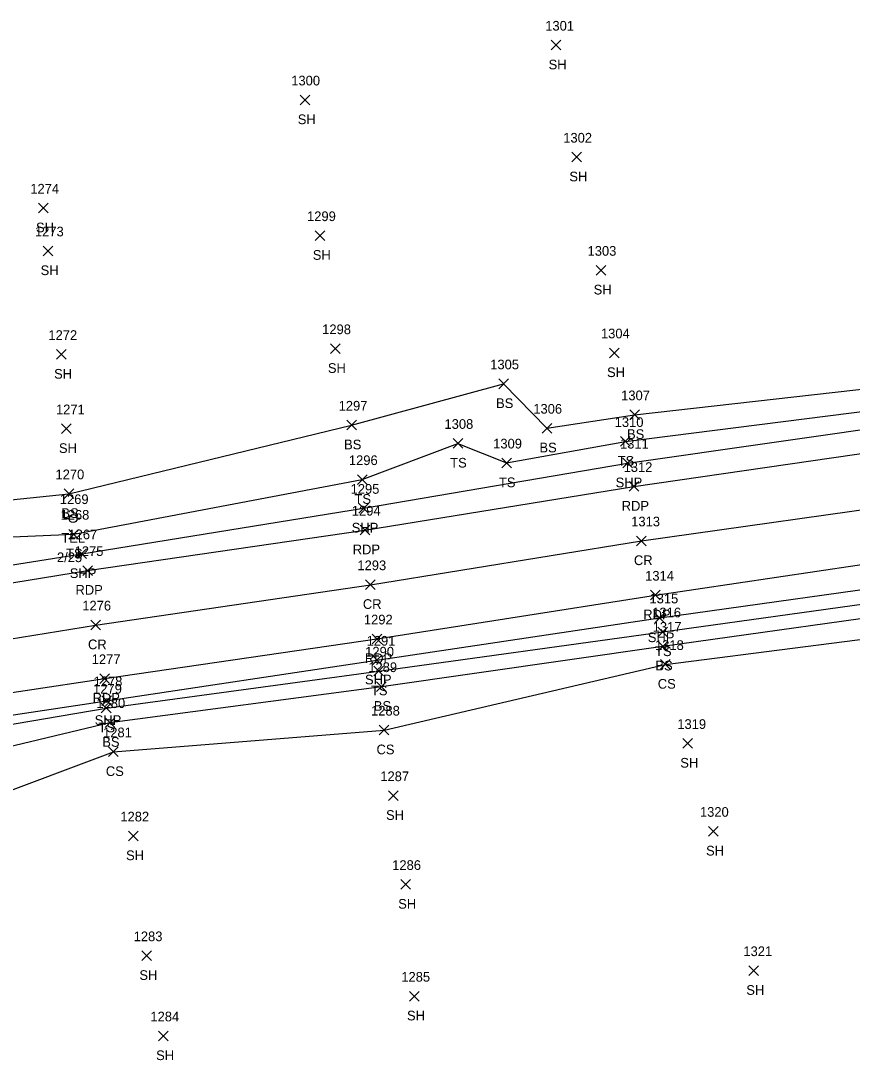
# Model space of a CAD drawing. Extents: x 1497084 to 1499861, y 734741 to 735567.
# Drawn here: x 1498487 to 1498658.8, y 735242.1 to 735456.8 of the extents above; entities that cross this region are included whole.
import ezdxf

# ---------------------------------------------------------------- set-up
doc = ezdxf.new("R2010")
doc.units = 0
for name, color, linetype in [('L_A', 7, 'Continuous'), ('L_I', 7, 'Continuous'), ('L_TIC', 7, 'Continuous'), ('LELB', 7, 'Continuous'), ('P_A', 7, 'Continuous'), ('P_I', 7, 'Continuous'), ('P_TIC', 7, 'Continuous'), ('PET', 7, 'Continuous'), ('PRC', 7, 'Continuous'), ('PSP', 7, 'Continuous'), ('U_A', 7, 'Continuous'), ('U_C', 7, 'Continuous'), ('U_I', 7, 'Continuous'), ('UP', 7, 'Continuous')]:
    doc.layers.add(name, color=color, linetype=linetype)

msp = doc.modelspace()

# ---------------------------------------------------------------- linework, layer by layer
at = {"layer": 'L_TIC'}
for points in [[(1498596.59, 735450.76), (1498598.59, 735452.76)], [(1498598.59, 735450.76), (1498596.59, 735452.76)], [(1498544.77, 735439.44), (1498546.77, 735441.44)], [(1498546.77, 735439.44), (1498544.77, 735441.44)], [(1498600.88, 735427.63), (1498602.88, 735429.63)], [(1498602.88, 735427.63), (1498600.88, 735429.63)], [(1498490.69, 735417.1), (1498492.69, 735419.1)], [(1498492.69, 735417.1), (1498490.69, 735419.1)], [(1498547.88, 735411.42), (1498549.88, 735413.42)], [(1498549.88, 735411.42), (1498547.88, 735413.42)], [(1498491.64, 735408.26), (1498493.64, 735410.26)], [(1498493.64, 735408.26), (1498491.64, 735410.26)], [(1498605.9, 735404.26), (1498607.9, 735406.26)], [(1498607.9, 735404.26), (1498605.9, 735406.26)], [(1498550.99, 735388.06), (1498552.99, 735390.06)], [(1498552.99, 735388.06), (1498550.99, 735390.06)], [(1498494.42, 735386.87), (1498496.42, 735388.87)], [(1498496.42, 735386.87), (1498494.42, 735388.87)], [(1498608.67, 735387.2), (1498610.67, 735389.2)], [(1498610.67, 735387.2), (1498608.67, 735389.2)], [(1498585.79, 735380.8), (1498587.79, 735382.8)], [(1498587.79, 735380.8), (1498585.79, 735382.8)], [(1498612.85, 735374.41), (1498614.85, 735376.41)], [(1498614.85, 735374.41), (1498612.85, 735376.41)], [(1498495.42, 735371.52), (1498497.42, 735373.52)], [(1498497.42, 735371.52), (1498495.42, 735373.52)], [(1498554.39, 735372.27), (1498556.39, 735374.27)], [(1498556.39, 735372.27), (1498554.39, 735374.27)], [(1498594.75, 735371.64), (1498596.75, 735373.64)], [(1498596.75, 735371.64), (1498594.75, 735373.64)], [(1498610.95, 735368.89), (1498612.95, 735370.89)], [(1498612.95, 735368.89), (1498610.95, 735370.89)], [(1498576.34, 735368.5), (1498578.34, 735370.5)], [(1498578.34, 735368.5), (1498576.34, 735370.5)], [(1498586.41, 735364.45), (1498588.41, 735366.45)], [(1498588.41, 735364.45), (1498586.41, 735366.45)], [(1498556.57, 735361.02), (1498558.57, 735363.02)], [(1498558.57, 735361.02), (1498556.57, 735363.02)], [(1498495.97, 735358.09), (1498497.97, 735360.09)], [(1498497.97, 735358.09), (1498495.97, 735360.09)], [(1498496.98, 735349.74), (1498498.98, 735351.74)], [(1498498.98, 735349.74), (1498496.98, 735351.74)], [(1498618.67, 735329.56), (1498620.67, 735331.56)], [(1498620.67, 735329.56), (1498618.67, 735331.56)], [(1498618.71, 735326.6), (1498620.71, 735328.6)], [(1498620.71, 735326.6), (1498618.71, 735328.6)], [(1498559.97, 735321.47), (1498561.97, 735323.47)], [(1498561.97, 735321.47), (1498559.97, 735323.47)], [(1498619.2, 735322.83), (1498621.2, 735324.83)], [(1498621.2, 735322.83), (1498619.2, 735324.83)], [(1498560.53, 735318.26), (1498562.53, 735320.26)], [(1498562.53, 735318.26), (1498560.53, 735320.26)], [(1498503.67, 735313.81), (1498505.67, 735315.81)], [(1498505.67, 735313.81), (1498503.67, 735315.81)], [(1498504.43, 735310.83), (1498506.43, 735312.83)], [(1498506.43, 735310.83), (1498504.43, 735312.83)], [(1498561.09, 735309.28), (1498563.09, 735311.28)], [(1498563.09, 735309.28), (1498561.09, 735311.28)], [(1498623.8, 735306.52), (1498625.8, 735308.52)], [(1498625.8, 735306.52), (1498623.8, 735308.52)], [(1498505.16, 735304.79), (1498507.16, 735306.79)], [(1498507.16, 735304.79), (1498505.16, 735306.79)], [(1498563.01, 735295.73), (1498565.01, 735297.73)], [(1498565.01, 735295.73), (1498563.01, 735297.73)], [(1498509.29, 735287.41), (1498511.29, 735289.41)], [(1498511.29, 735287.41), (1498509.29, 735289.41)], [(1498629.13, 735288.37), (1498631.13, 735290.37)], [(1498631.13, 735288.37), (1498629.13, 735290.37)], [(1498565.52, 735277.39), (1498567.52, 735279.39)], [(1498567.52, 735277.39), (1498565.52, 735279.39)], [(1498512.05, 735262.67), (1498514.05, 735264.67)], [(1498514.05, 735262.67), (1498512.05, 735264.67)], [(1498637.44, 735259.59), (1498639.44, 735261.59)], [(1498639.44, 735259.59), (1498637.44, 735261.59)], [(1498567.34, 735254.31), (1498569.34, 735256.31)], [(1498569.34, 735254.31), (1498567.34, 735256.31)], [(1498515.5, 735246.11), (1498517.5, 735248.11)], [(1498517.5, 735246.11), (1498515.5, 735248.11)]]:
    msp.add_lwpolyline(points, dxfattribs=at)
at = {"layer": 'LELB'}
for points in [[(1498337.56, 735327.03), (1498345.07, 735328.8), (1498360.02, 735336.05), (1498371.93, 735339.18), (1498383.26, 735341.12), (1498406.51, 735345.51), (1498447.67, 735353.97), (1498496.97, 735359.09), (1498555.39, 735373.27), (1498586.79, 735381.8), (1498595.75, 735372.64), (1498613.85, 735375.41), (1498671.76, 735381.92), (1498728.97, 735390.65), (1498788.67, 735399.74), (1498809.3, 735404.43), (1498807.97, 735434.2)], [(1498337.34, 735322.86), (1498344.97, 735324.75), (1498384.58, 735334.28), (1498409.2, 735337.4), (1498355.01, 735326.99), (1498382.45, 735331.79), (1498397.41, 735335.39), (1498428.62, 735342.29), (1498447.37, 735348.53), (1498497.98, 735350.74), (1498557.57, 735362.02), (1498577.34, 735369.5), (1498587.41, 735365.45), (1498611.95, 735369.89), (1498672.2, 735377.52), (1498729.57, 735386.75), (1498788.99, 735396.46), (1498814.15, 735401.69), (1498836.02, 735409.82), (1498851.62, 735410.69)], [(1498435.91, 735287.74), (1498479.86, 735295.91), (1498506.16, 735305.79), (1498562.09, 735310.28), (1498620.2, 735323.83), (1498678.14, 735331.24), (1498740.72, 735343.34), (1498795.48, 735350.02), (1498845.2, 735354.12), (1498873.2, 735358.8), (1498904.58, 735361.51), (1498941.92, 735355.1), (1499002.35, 735368.44), (1499018.4, 735380.28), (1499017.69, 735389.23)], [(1498348.47, 735290.66), (1498349.3, 735292.12), (1498356.63, 735290), (1498367.4, 735288.15), (1498383.02, 735293.44), (1498402.41, 735293.85), (1498412.25, 735297.62), (1498434.81, 735303.59), (1498479.54, 735310.53), (1498504.67, 735314.81), (1498560.97, 735322.47), (1498619.67, 735330.56), (1498677.12, 735338.58), (1498739.34, 735349.1), (1498794.83, 735357.09), (1498843.56, 735364.4), (1498863.08, 735369.39)], [(1498347.81, 735289.73), (1498349.19, 735291.09), (1498355.19, 735287.19), (1498360.89, 735284.04), (1498368.96, 735282.7), (1498386.86, 735285.14), (1498402.12, 735288.93), (1498434.54, 735297.05), (1498479.17, 735305.56), (1498505.43, 735311.83), (1498561.53, 735319.26), (1498619.71, 735327.6), (1498677.77, 735335.72), (1498739.77, 735346.92), (1498794.9, 735353.46), (1498843.96, 735361.06), (1498867.57, 735365.18)]]:
    msp.add_lwpolyline(points, dxfattribs=at)
at = {"layer": 'P_TIC'}
for points in [[(1498611.39, 735364.43), (1498613.39, 735366.43)], [(1498613.39, 735364.43), (1498611.39, 735366.43)], [(1498612.71, 735359.6), (1498614.71, 735361.6)], [(1498614.71, 735359.6), (1498612.71, 735361.6)], [(1498556.87, 735355.09), (1498558.87, 735357.09)], [(1498558.87, 735355.09), (1498556.87, 735357.09)], [(1498557.12, 735350.59), (1498559.12, 735352.59)], [(1498559.12, 735350.59), (1498557.12, 735352.59)], [(1498614.27, 735348.36), (1498616.27, 735350.36)], [(1498616.27, 735348.36), (1498614.27, 735350.36)], [(1498498.61, 735345.69), (1498500.61, 735347.69)], [(1498500.61, 735345.69), (1498498.61, 735347.69)], [(1498499.84, 735342.24), (1498501.84, 735344.24)], [(1498501.84, 735342.24), (1498499.84, 735344.24)], [(1498558.28, 735339.31), (1498560.28, 735341.31)], [(1498560.28, 735339.31), (1498558.28, 735341.31)], [(1498617.15, 735337.15), (1498619.15, 735339.15)], [(1498619.15, 735337.15), (1498617.15, 735339.15)], [(1498618.04, 735332.45), (1498620.04, 735334.45)], [(1498620.04, 735332.45), (1498618.04, 735334.45)], [(1498501.48, 735330.98), (1498503.48, 735332.98)], [(1498503.48, 735330.98), (1498501.48, 735332.98)], [(1498559.62, 735328.11), (1498561.62, 735330.11)], [(1498561.62, 735328.11), (1498559.62, 735330.11)], [(1498559.61, 735323.72), (1498561.61, 735325.72)], [(1498561.61, 735323.72), (1498559.61, 735325.72)], [(1498503.37, 735319.92), (1498505.37, 735321.92)], [(1498505.37, 735319.92), (1498503.37, 735321.92)], [(1498503.77, 735315.34), (1498505.77, 735317.34)], [(1498505.77, 735315.34), (1498503.77, 735317.34)]]:
    msp.add_lwpolyline(points, dxfattribs=at)
at = {"layer": 'PET'}
for points in [[(1498338.16, 735318.88), (1498357.92, 735321.69), (1498398.8, 735327.5), (1498451.3, 735335.22), (1498500.84, 735343.24), (1498558.12, 735351.59), (1498613.71, 735360.6), (1498673.07, 735369.22), (1498732.2, 735378.98), (1498789.96, 735387.82), (1498838.32, 735395.91), (1498888.99, 735404.3)], [(1498338.16, 735318.88), (1498339.87, 735308.1), (1498341.54, 735297.2), (1498360.21, 735300.18), (1498403.13, 735306.7), (1498454.97, 735313.53), (1498504.37, 735320.92), (1498560.62, 735329.11), (1498618.15, 735338.15), (1498676.47, 735346.79), (1498736.79, 735356.32), (1498793.85, 735365.14), (1498842.44, 735373.21), (1498892.67, 735381.87)]]:
    msp.add_lwpolyline(points, dxfattribs=at)
at = {"layer": 'PRC'}
msp.add_lwpolyline([(1498339.87, 735308.1), (1498359.7, 735310.92), (1498400.74, 735317.79), (1498454.01, 735324.13), (1498502.48, 735331.98), (1498559.28, 735340.31), (1498615.27, 735349.36), (1498674.88, 735357.8), (1498734.12, 735367.05), (1498791.71, 735376.05), (1498839.89, 735384.37), (1498890.74, 735392.79)], dxfattribs=at)
at = {"layer": 'PSP'}
for points in [[(1498357.92, 735321.69), (1498398.08, 735329.19), (1498452.34, 735339.17), (1498499.61, 735346.69), (1498557.87, 735356.09), (1498612.39, 735365.43), (1498672.54, 735374.02), (1498730.82, 735383.15), (1498789.68, 735392.14), (1498809.84, 735395.77), (1498833.8, 735399.85), (1498855.6, 735403.69)], [(1498360.21, 735300.18), (1498403.51, 735303.5), (1498455.72, 735308.98), (1498504.77, 735316.34), (1498560.61, 735324.72), (1498619.04, 735333.45), (1498677.11, 735341.57), (1498738.32, 735351.55), (1498794.38, 735360.63), (1498843.61, 735368.57), (1498860.46, 735371.23)]]:
    msp.add_lwpolyline(points, dxfattribs=at)
at = {"layer": 'UP'}
for p, q in [((1498496.18, 735353.96), (1498497.01, 735353.96)), ((1498497.84, 735353.97), (1498497.84, 735353.97)), ((1498499.51, 735353.97), (1498498.67, 735353.97)), ((1498498.67, 735353.97), (1498498.67, 735353.97)), ((1498499.51, 735353.97), (1498499.51, 735353.97))]:
    msp.add_line(p, q, dxfattribs=at)
msp.add_circle((1498497.84, 735353.97), 0.833, dxfattribs=at)

# ---------------------------------------------------------------- texts
at = {"layer": 'L_A'}
for s, p in [('SH', (1498596.08, 735446.76)), ('SH', (1498544.26, 735435.44)), ('SH', (1498600.37, 735423.63)), ('SH', (1498490.18, 735413.1)), ('SH', (1498547.36, 735407.42)), ('SH', (1498491.13, 735404.26)), ('SH', (1498605.39, 735400.26)), ('SH', (1498550.48, 735384.06)), ('SH', (1498493.91, 735382.87)), ('SH', (1498608.16, 735383.2)), ('BS', (1498585.23, 735376.8)), ('BS', (1498612.29, 735370.41)), ('SH', (1498494.91, 735367.52)), ('BS', (1498553.83, 735368.27)), ('BS', (1498594.19, 735367.64)), ('TS', (1498575.75, 735364.5)), ('TS', (1498610.36, 735364.89)), ('TS', (1498585.82, 735360.45)), ('TS', (1498555.98, 735357.02)), ('BS', (1498495.41, 735354.09)), ('TS', (1498496.39, 735345.74)), ('TS', (1498618.08, 735325.56)), ('BS', (1498618.15, 735322.6)), ('TS', (1498559.38, 735317.47)), ('CS', (1498618.64, 735318.83)), ('BS', (1498559.97, 735314.26)), ('TS', (1498503.08, 735309.81)), ('BS', (1498503.87, 735306.83)), ('CS', (1498560.53, 735305.28)), ('SH', (1498623.29, 735302.52)), ('CS', (1498504.6, 735300.79)), ('SH', (1498562.49, 735291.73)), ('SH', (1498508.78, 735283.41)), ('SH', (1498628.62, 735284.37)), ('SH', (1498565.01, 735273.39)), ('SH', (1498511.53, 735258.67)), ('SH', (1498636.93, 735255.59)), ('SH', (1498566.83, 735250.31)), ('SH', (1498514.99, 735242.11))]:
    msp.add_text(s, height=2, dxfattribs=at).set_placement(p)
at = {"layer": 'L_I'}
for s, p in [('1301', (1498595.39, 735454.76)), ('1300', (1498542.91, 735443.44)), ('1302', (1498599.11, 735431.63)), ('1274', (1498488.99, 735421.1)), ('1299', (1498546.17, 735415.42)), ('1273', (1498489.95, 735412.26)), ('1303', (1498604.13, 735408.26)), ('1272', (1498492.73, 735390.87)), ('1298', (1498549.3, 735392.06)), ('1304', (1498606.9, 735391.2)), ('1305', (1498584.02, 735384.8)), ('1307', (1498611.07, 735378.41)), ('1271', (1498494.3, 735375.52)), ('1297', (1498552.7, 735376.27)), ('1306', (1498592.92, 735375.64)), ('1308', (1498574.57, 735372.5)), ('1310', (1498609.74, 735372.89)), ('1309', (1498584.63, 735368.45)), ('1296', (1498554.82, 735365.02)), ('1270', (1498494.19, 735362.09)), ('1268', (1498495.24, 735353.74)), ('1316', (1498617.49, 735333.56)), ('1317', (1498617.59, 735330.6)), ('1318', (1498618.07, 735326.83)), ('1290', (1498558.19, 735325.47)), ('1289', (1498558.83, 735322.26)), ('1279', (1498501.97, 735317.81)), ('1280', (1498502.65, 735314.83)), ('1288', (1498559.4, 735313.28)), ('1281', (1498504.03, 735308.79)), ('1319', (1498622.67, 735310.52)), ('1287', (1498561.31, 735299.73)), ('1282', (1498507.6, 735291.41)), ('1320', (1498627.35, 735292.37)), ('1286', (1498563.77, 735281.39)), ('1283', (1498510.35, 735266.67)), ('1321', (1498636.32, 735263.59)), ('1285', (1498565.65, 735258.31)), ('1284', (1498513.81, 735250.11))]:
    msp.add_text(s, height=2, dxfattribs=at).set_placement(p)
at = {"layer": 'P_A'}
for s, p in [('SHP', (1498609.93, 735360.43)), ('RDP', (1498611.19, 735355.6)), ('SHP', (1498555.4, 735351.09)), ('RDP', (1498555.61, 735346.59)), ('CR', (1498613.71, 735344.36)), ('SHP', (1498497.15, 735341.69)), ('RDP', (1498498.33, 735338.24)), ('CR', (1498557.71, 735335.31)), ('RDP', (1498615.64, 735333.15)), ('SHP', (1498616.58, 735328.45)), ('CR', (1498500.91, 735326.98)), ('RDP', (1498558.11, 735324.11)), ('SHP', (1498558.14, 735319.72)), ('RDP', (1498501.86, 735315.92)), ('SHP', (1498502.3, 735311.34))]:
    msp.add_text(s, height=2, dxfattribs=at).set_placement(p)
at = {"layer": 'P_I'}
for s, p in [('1311', (1498610.83, 735368.43)), ('1312', (1498611.58, 735363.6)), ('1295', (1498555.17, 735359.09)), ('1294', (1498555.43, 735354.59)), ('1313', (1498613.15, 735352.36)), ('1267', (1498496.87, 735349.69)), ('1275', (1498498.15, 735346.24)), ('1293', (1498556.58, 735343.31)), ('1314', (1498616.03, 735341.15)), ('1315', (1498616.92, 735336.45)), ('1276', (1498499.73, 735334.98)), ('1292', (1498557.92, 735332.11)), ('1291', (1498558.48, 735327.72)), ('1277', (1498501.68, 735323.92)), ('1278', (1498502.07, 735319.34))]:
    msp.add_text(s, height=2, dxfattribs=at).set_placement(p)
at = {"layer": 'U_A'}
msp.add_text('TEL', height=2, dxfattribs=at).set_placement((1498495.4, 735348.97))
at = {"layer": 'U_C'}
msp.add_text('2/25', height=2, dxfattribs=at).set_placement((1498494.5, 735344.97))
at = {"layer": 'U_I'}
msp.add_text('1269', height=2, dxfattribs=at).set_placement((1498495.09, 735356.97))

doc.saveas('drawing.dxf')
